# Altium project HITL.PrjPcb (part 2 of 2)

## Sheet HITL (MUX) SH4.SchDoc
size Tabloid; SheetNumber: 4; SheetTotal: 7
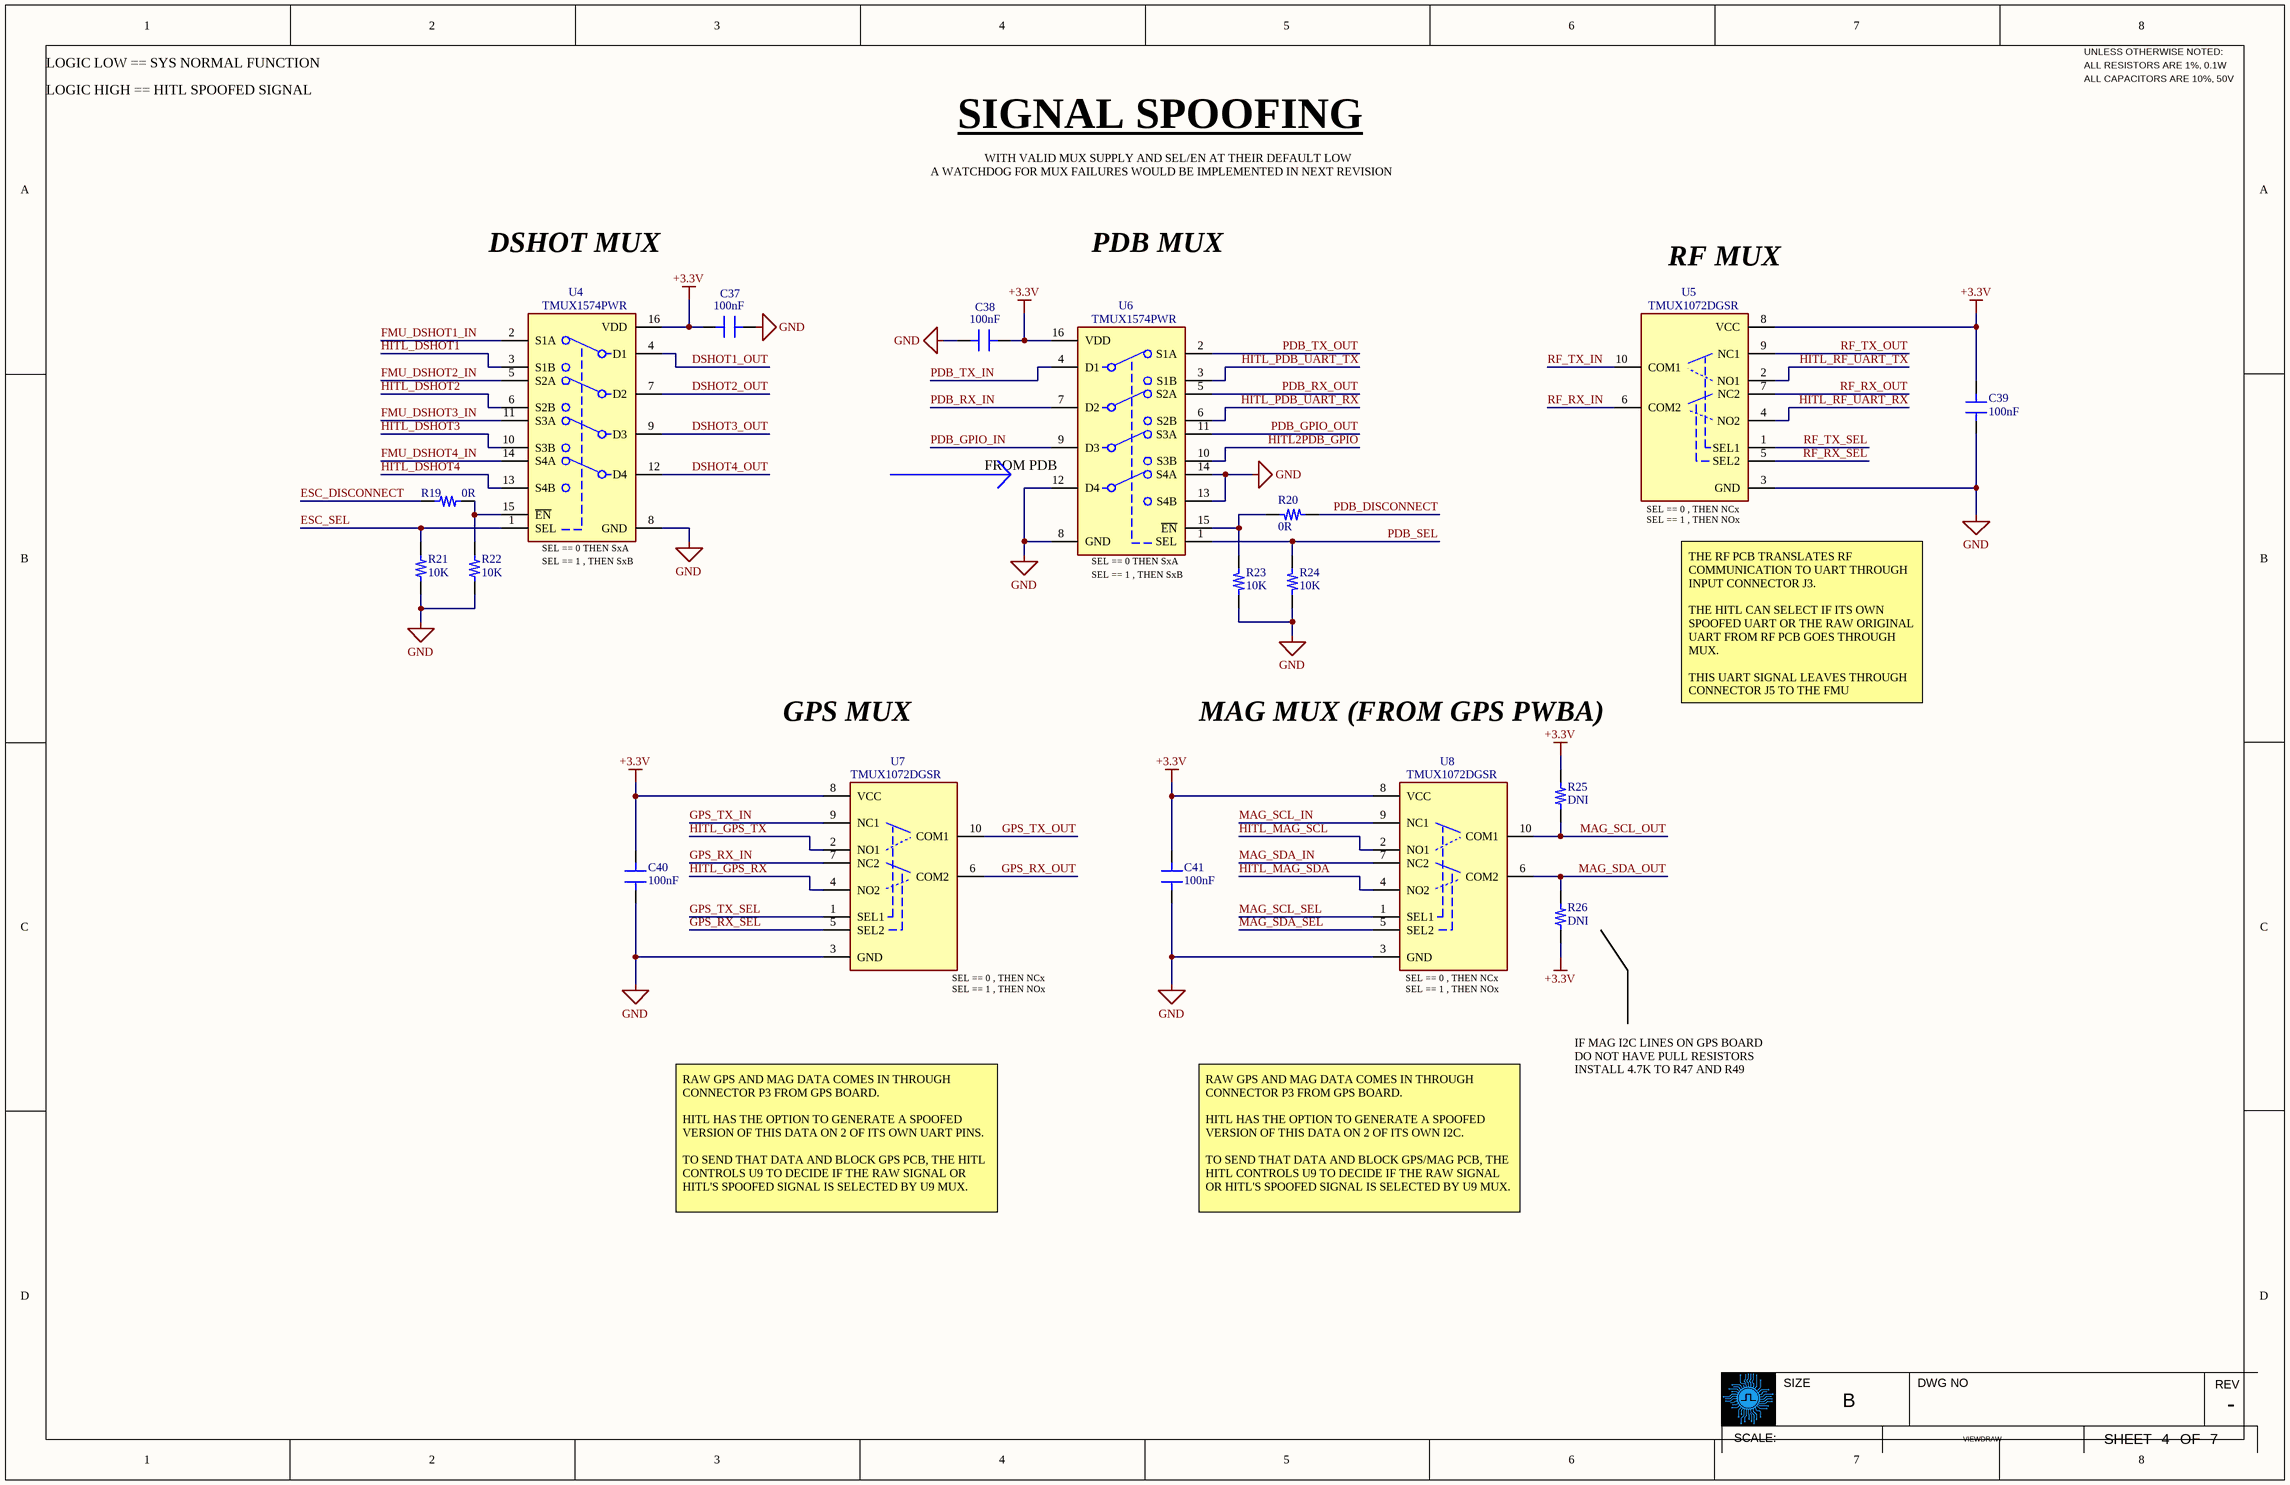
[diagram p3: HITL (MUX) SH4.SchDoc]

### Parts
C37  100nF  [0603]
C38  100nF  [0603]
C39  100nF  [0603]
C40  100nF  [0603]
C41  100nF  [0603]
R19  0R  [0603]
R20  0R  [0603]
R21  10K  [0603]
R22  10K  [0603]
R23  10K  [0603]
R24  10K  [0603]
R25  DNI  [0603]
R26  DNI  [0603]
U4  TMUX1574PWR  [SOP65P640X120-16N]
U5  TMUX1072DGSR  [SOP50P490X110-10N]
U6  TMUX1574PWR  [SOP65P640X120-16N]
U7  TMUX1072DGSR  [SOP50P490X110-10N]
U8  TMUX1072DGSR  [SOP50P490X110-10N]

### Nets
+3.3V: C37.1 C38.1 C39.2 C40.2 C41.2 R25.1 R26.2 U4.16(VDD) U5.8(VCC) U6.16(VDD) U7.8(VCC) U8.8(VCC)
GND: C37.2 C38.2 C39.1 C40.1 C41.1 R21.1 R22.1 R23.1 R24.1 U4.8(GND) U5.3(GND) U6.8(GND) U6.12(D4) U6.13(S4B) U6.14(S4A) U7.3(GND) U8.3(GND)
DSHOT1_OUT: U4.4(D1)
DSHOT2_OUT: U4.7(D2)
DSHOT3_OUT: U4.9(D3)
DSHOT4_OUT: U4.12(D4)
ESC_DISCONNECT: R19.2
ESC_SEL: R21.2 U4.1(SEL)
FMU_DSHOT1_IN: U4.2(S1A)
FMU_DSHOT2_IN: U4.5(S2A)
FMU_DSHOT3_IN: U4.11(S3A)
FMU_DSHOT4_IN: U4.14(S4A)
GPS_RX_IN: U7.7(NC2)
GPS_RX_OUT: U7.6(COM2)
GPS_RX_SEL: U7.5(SEL2)
GPS_TX_IN: U7.9(NC1)
GPS_TX_OUT: U7.10(COM1)
GPS_TX_SEL: U7.1(SEL1)
HITL2PDB_GPIO: U6.10(S3B)
HITL_DSHOT1: U4.3(S1B)
HITL_DSHOT2: U4.6(S2B)
HITL_DSHOT3: U4.10(S3B)
HITL_DSHOT4: U4.13(S4B)
HITL_GPS_RX: U7.4(NO2)
HITL_GPS_TX: U7.2(NO1)
HITL_MAG_SCL: U8.2(NO1)
HITL_MAG_SDA: U8.4(NO2)
HITL_PDB_UART_RX: U6.6(S2B)
HITL_PDB_UART_TX: U6.3(S1B)
HITL_RF_UART_RX: U5.4(NO2)
HITL_RF_UART_TX: U5.2(NO1)
MAG_SCL_IN: U8.9(NC1)
MAG_SCL_OUT: R25.2 U8.10(COM1)
MAG_SCL_SEL: U8.1(SEL1)
MAG_SDA_IN: U8.7(NC2)
MAG_SDA_OUT: R26.1 U8.6(COM2)
MAG_SDA_SEL: U8.5(SEL2)
PDB_DISCONNECT: R20.2
PDB_GPIO_IN: U6.9(D3)
PDB_GPIO_OUT: U6.11(S3A)
PDB_RX_IN: U6.7(D2)
PDB_RX_OUT: U6.5(S2A)
PDB_SEL: R24.2 U6.1(SEL)
PDB_TX_IN: U6.4(D1)
PDB_TX_OUT: U6.2(S1A)
RF_RX_IN: U5.6(COM2)
RF_RX_OUT: U5.7(NC2)
RF_RX_SEL: U5.5(SEL2)
RF_TX_IN: U5.10(COM1)
RF_TX_OUT: U5.9(NC1)
RF_TX_SEL: U5.1(SEL1)
NetR19_1: R19.1 R22.2 U4.15(~{EN})
NetR20_1: R20.1 R23.2 U6.15(~{EN})

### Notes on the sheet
- LOGIC LOW == SYS NORMAL FUNCTION
- LOGIC HIGH == HITL SPOOFED SIGNAL
- SIGNAL SPOOFING
- WITH VALID MUX SUPPLY AND SEL/EN AT THEIR DEFAULT LOW
- A WATCHDOG FOR MUX FAILURES WOULD BE IMPLEMENTED IN NEXT REVISION
- DSHOT MUX
- PDB MUX
- RF MUX
- FROM PDB
- (near U4) SEL == 0 THEN SxA
- (near U4) SEL == 1 , THEN SxB
- (near U6) SEL == 0 THEN SxA
- (near U5) SEL == 0 , THEN NCx
- (near U5) SEL == 1 , THEN NOx
- (near U6) SEL == 1 , THEN SxB
- THE RF PCB TRANSLATES RF COMMUNICATION TO UART THROUGH INPUT CONNECTOR J3.
  THE HITL CAN SELECT IF ITS OWN SPOOFED UART OR THE RAW ORIGINAL UART FROM RF PCB GOES THROUGH MUX.
  THIS UART SIGNAL LEAVES THROUGH CONNECTOR J5 TO THE FMU
- GPS MUX
- MAG MUX (FROM GPS PWBA)
- (near U7) SEL == 0 , THEN NCx
- (near U7) SEL == 1 , THEN NOx
- (near U8) SEL == 0 , THEN NCx
- (near U8) SEL == 1 , THEN NOx
- IF MAG I2C LINES ON GPS BOARD
- DO NOT HAVE PULL RESISTORS
- INSTALL 4.7K TO R47 AND R49
- RAW GPS AND MAG DATA COMES IN THROUGH CONNECTOR P3 FROM GPS BOARD.
  HITL HAS THE OPTION TO GENERATE A SPOOFED VERSION OF THIS DATA ON 2 OF ITS OWN UART PINS.
  TO SEND THAT DATA AND BLOCK GPS PCB, THE HITL CONTROLS U9 TO DECIDE IF THE RAW SIGNAL OR HITL'S SPOOFED SIGNAL IS SELECTED BY U9 MUX.
- RAW GPS AND MAG DATA COMES IN THROUGH CONNECTOR P3 FROM GPS BOARD.
  HITL HAS THE OPTION TO GENERATE A SPOOFED VERSION OF THIS DATA ON 2 OF ITS OWN I2C.
  TO SEND THAT DATA AND BLOCK GPS/MAG PCB, THE HITL CONTROLS U9 TO DECIDE IF THE RAW SIGNAL OR HITL'S SPOOFED SIGNAL IS SELECTED BY U9 MUX.
- -
- 4
- 7

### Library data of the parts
C37-C41 = 0603_C
R19-R26 = 0603_R
U4 U6 = TMUX1574PWR: 5-V, 2:1 (SPDT), 4-channel analog switch with powered-off protection & 1.8-V input logic; MF: Texas Instruments
U5 U7 U8 = TMUX1072DGSR: 5-V, 2:1 (SPDT), 2-channel analog switch with powered-off protection; MF: Texas Instruments

## Sheet HITL (MEMORY) SH5.SchDoc
size Tabloid; SheetNumber: 5; SheetTotal: 7
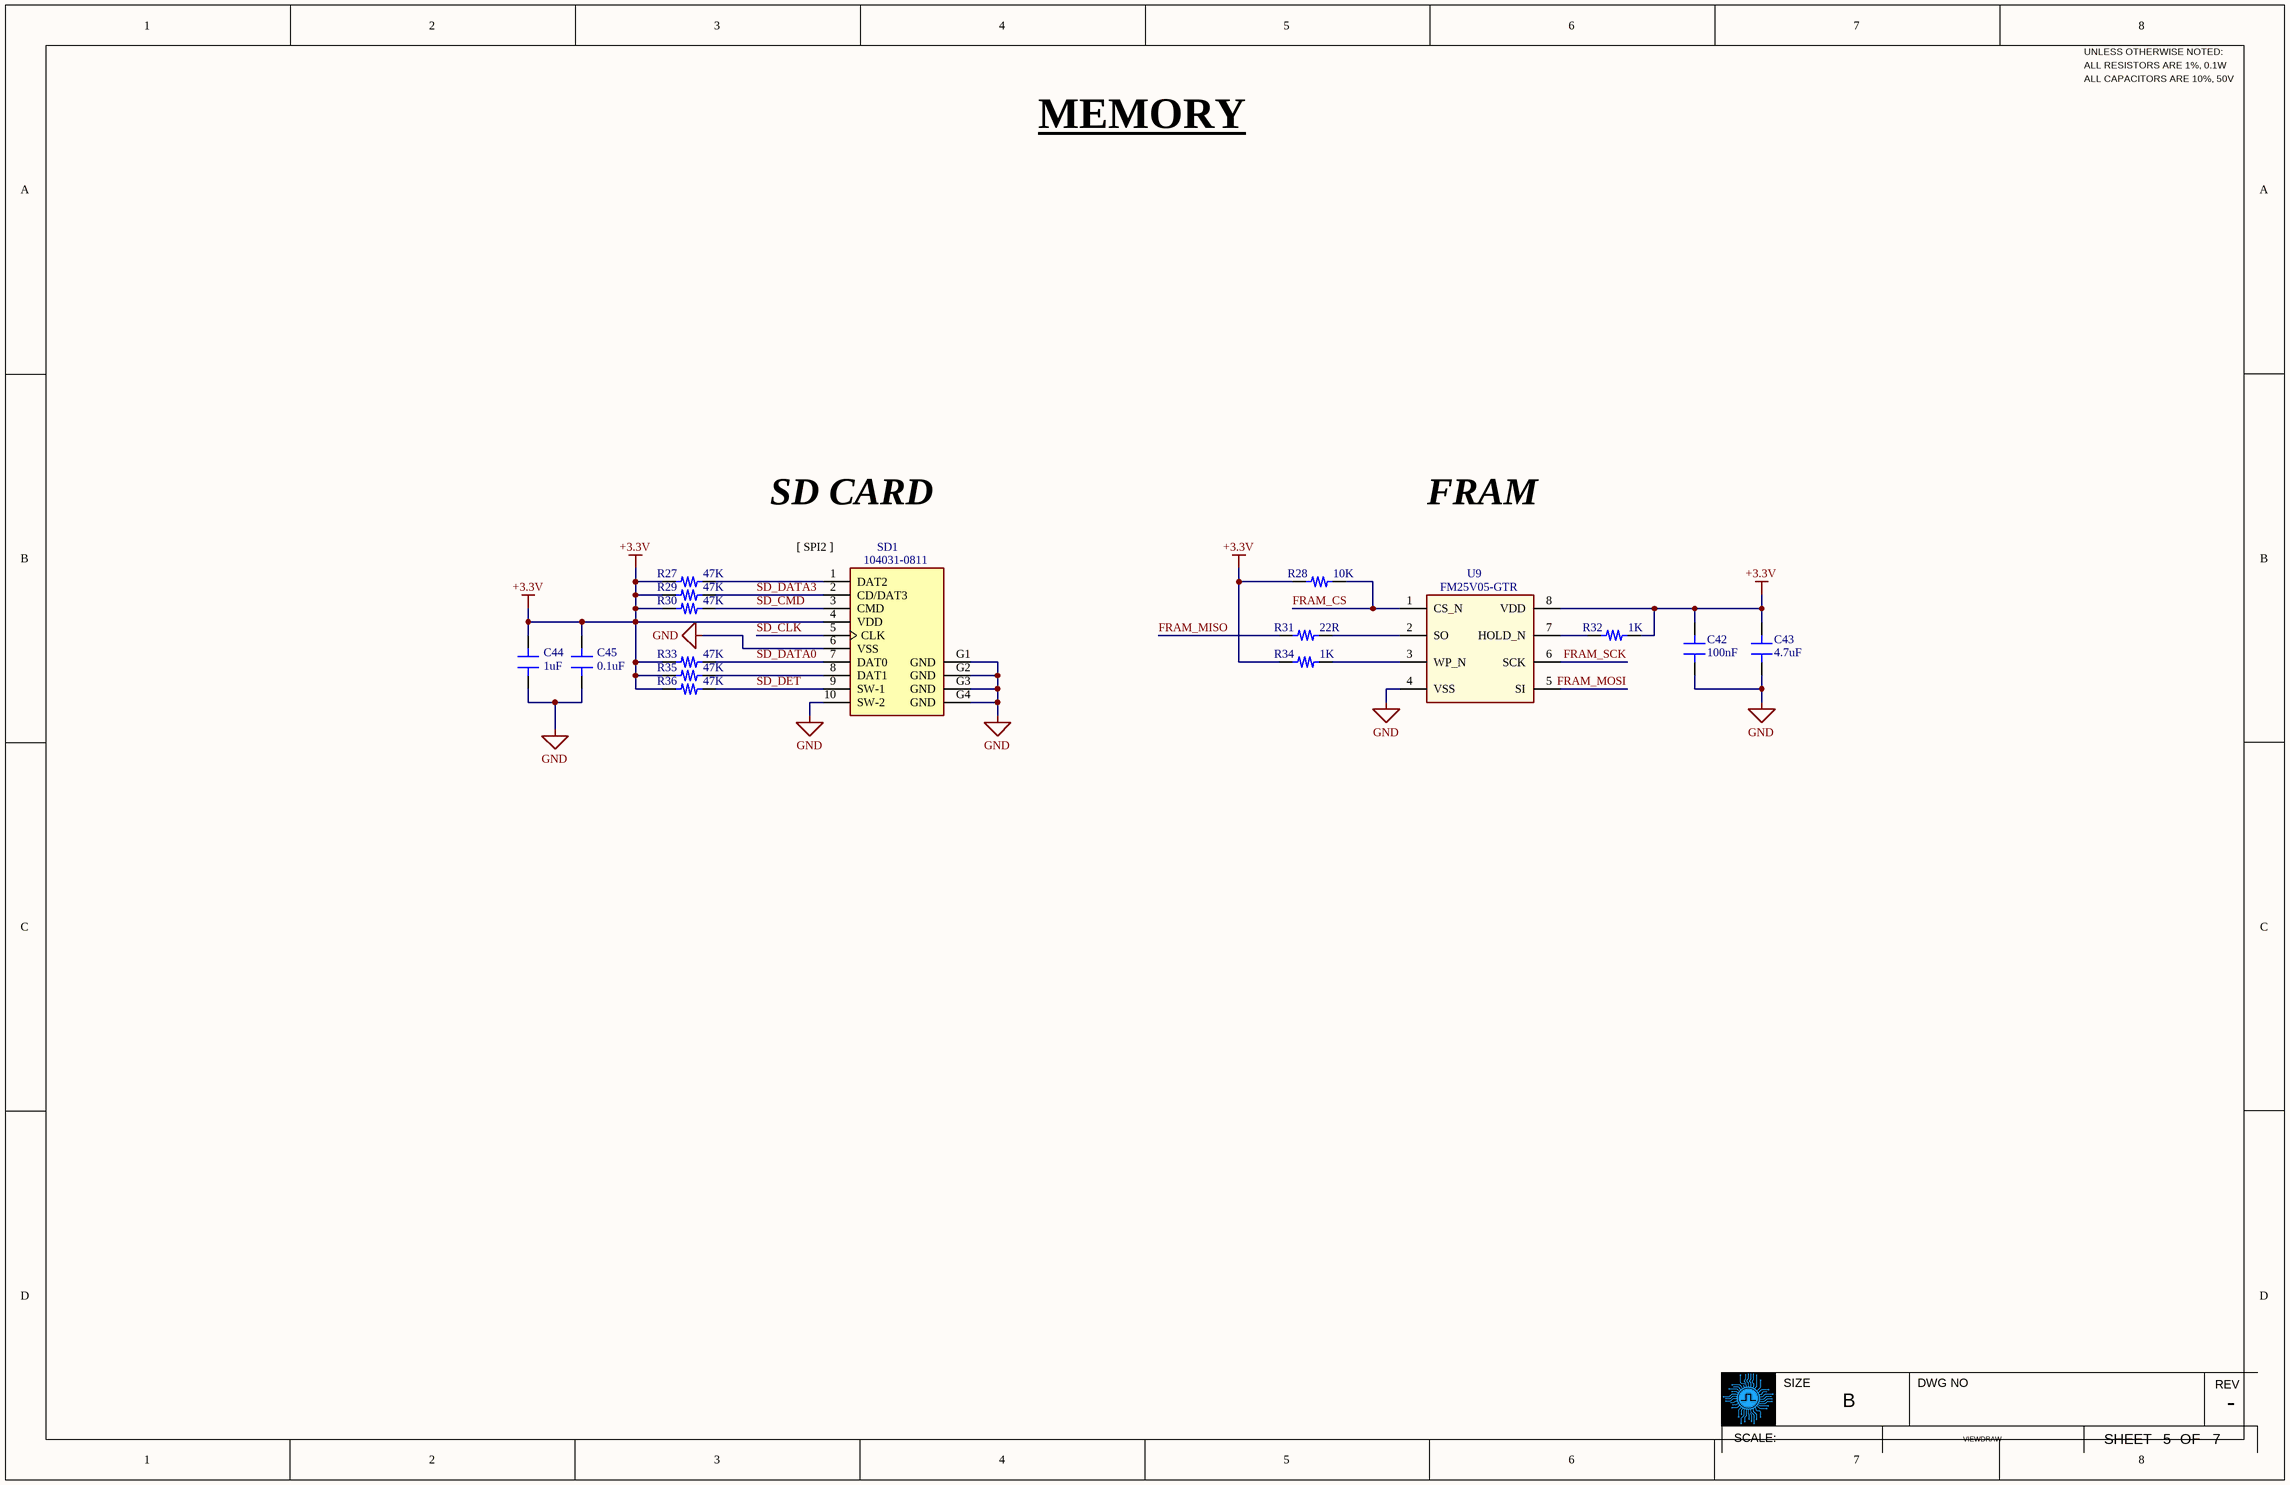
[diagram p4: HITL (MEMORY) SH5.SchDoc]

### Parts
C42  100nF  [0603]
C43  4.7uF  [0603]
C44  1uF  [0603]
C45  0.1uF  [0603]
R27  47K  [0603]
R28  10K  [0603]
R29  47K  [0603]
R30  47K  [0603]
R31  22R  [0603]
R32  1K  [0603]
R33  47K  [0603]
R34  1K  [0603]
R35  47K  [0603]
R36  47K  [0603]
SD1  104031-0811  [MOLEX_104031-0811]
U9  FM25V05-GTR  [SOIC127P602X173-8N-1-V]

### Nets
+3.3V: C42.2 C43.2 C44.2 C45.2 R27.1 R28.1 R29.1 R30.1 R32.2 R33.1 R34.1 R35.1 R36.1 SD1.4(VDD) U9.8(VDD)
GND: C42.1 C43.1 C44.1 C45.1 SD1.6(VSS) SD1.10(SW-2) SD1.G1(GND) SD1.G2(GND) SD1.G3(GND) SD1.G4(GND) U9.4(VSS)
FRAM_CS: R28.2 U9.1(CS_N)
FRAM_MISO: R31.1
FRAM_MOSI: U9.5(SI)
FRAM_SCK: U9.6(SCK)
SD_CLK: SD1.5(CLK)
SD_CMD: R30.2 SD1.3(CMD)
SD_DATA0: R33.2 SD1.7(DAT0)
SD_DATA3: R29.2 SD1.2(CD/DAT3)
SD_DET: R36.2 SD1.9(SW-1)
NetR27_2: R27.2 SD1.1(DAT2)
NetR31_2: R31.2 U9.2(SO)
NetR32_1: R32.1 U9.7(HOLD_N)
NetR34_2: R34.2 U9.3(WP_N)
NetR35_2: R35.2 SD1.8(DAT1)

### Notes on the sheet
- MEMORY
- SD CARD
- (near SD1) [ SPI2 ]
- FRAM
- -
- 5
- 7

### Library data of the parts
C42-C45 = 0603_C
R27-R36 = 0603_R
SD1 = 104031-0811: Surface Mount Micro SD Card Connector, with Push In Termination ¦ Molex Incorporated 104031-0811
U9 = FM25V05-GTR: 4-Kbit (512 × 8) Serial (SPI) F-RAM; Manufacturer: Infineon Technologies

## Sheet HITL (INTRFACE 1) SH6.SchDoc
size Tabloid; SheetNumber: 6; SheetTotal: 7
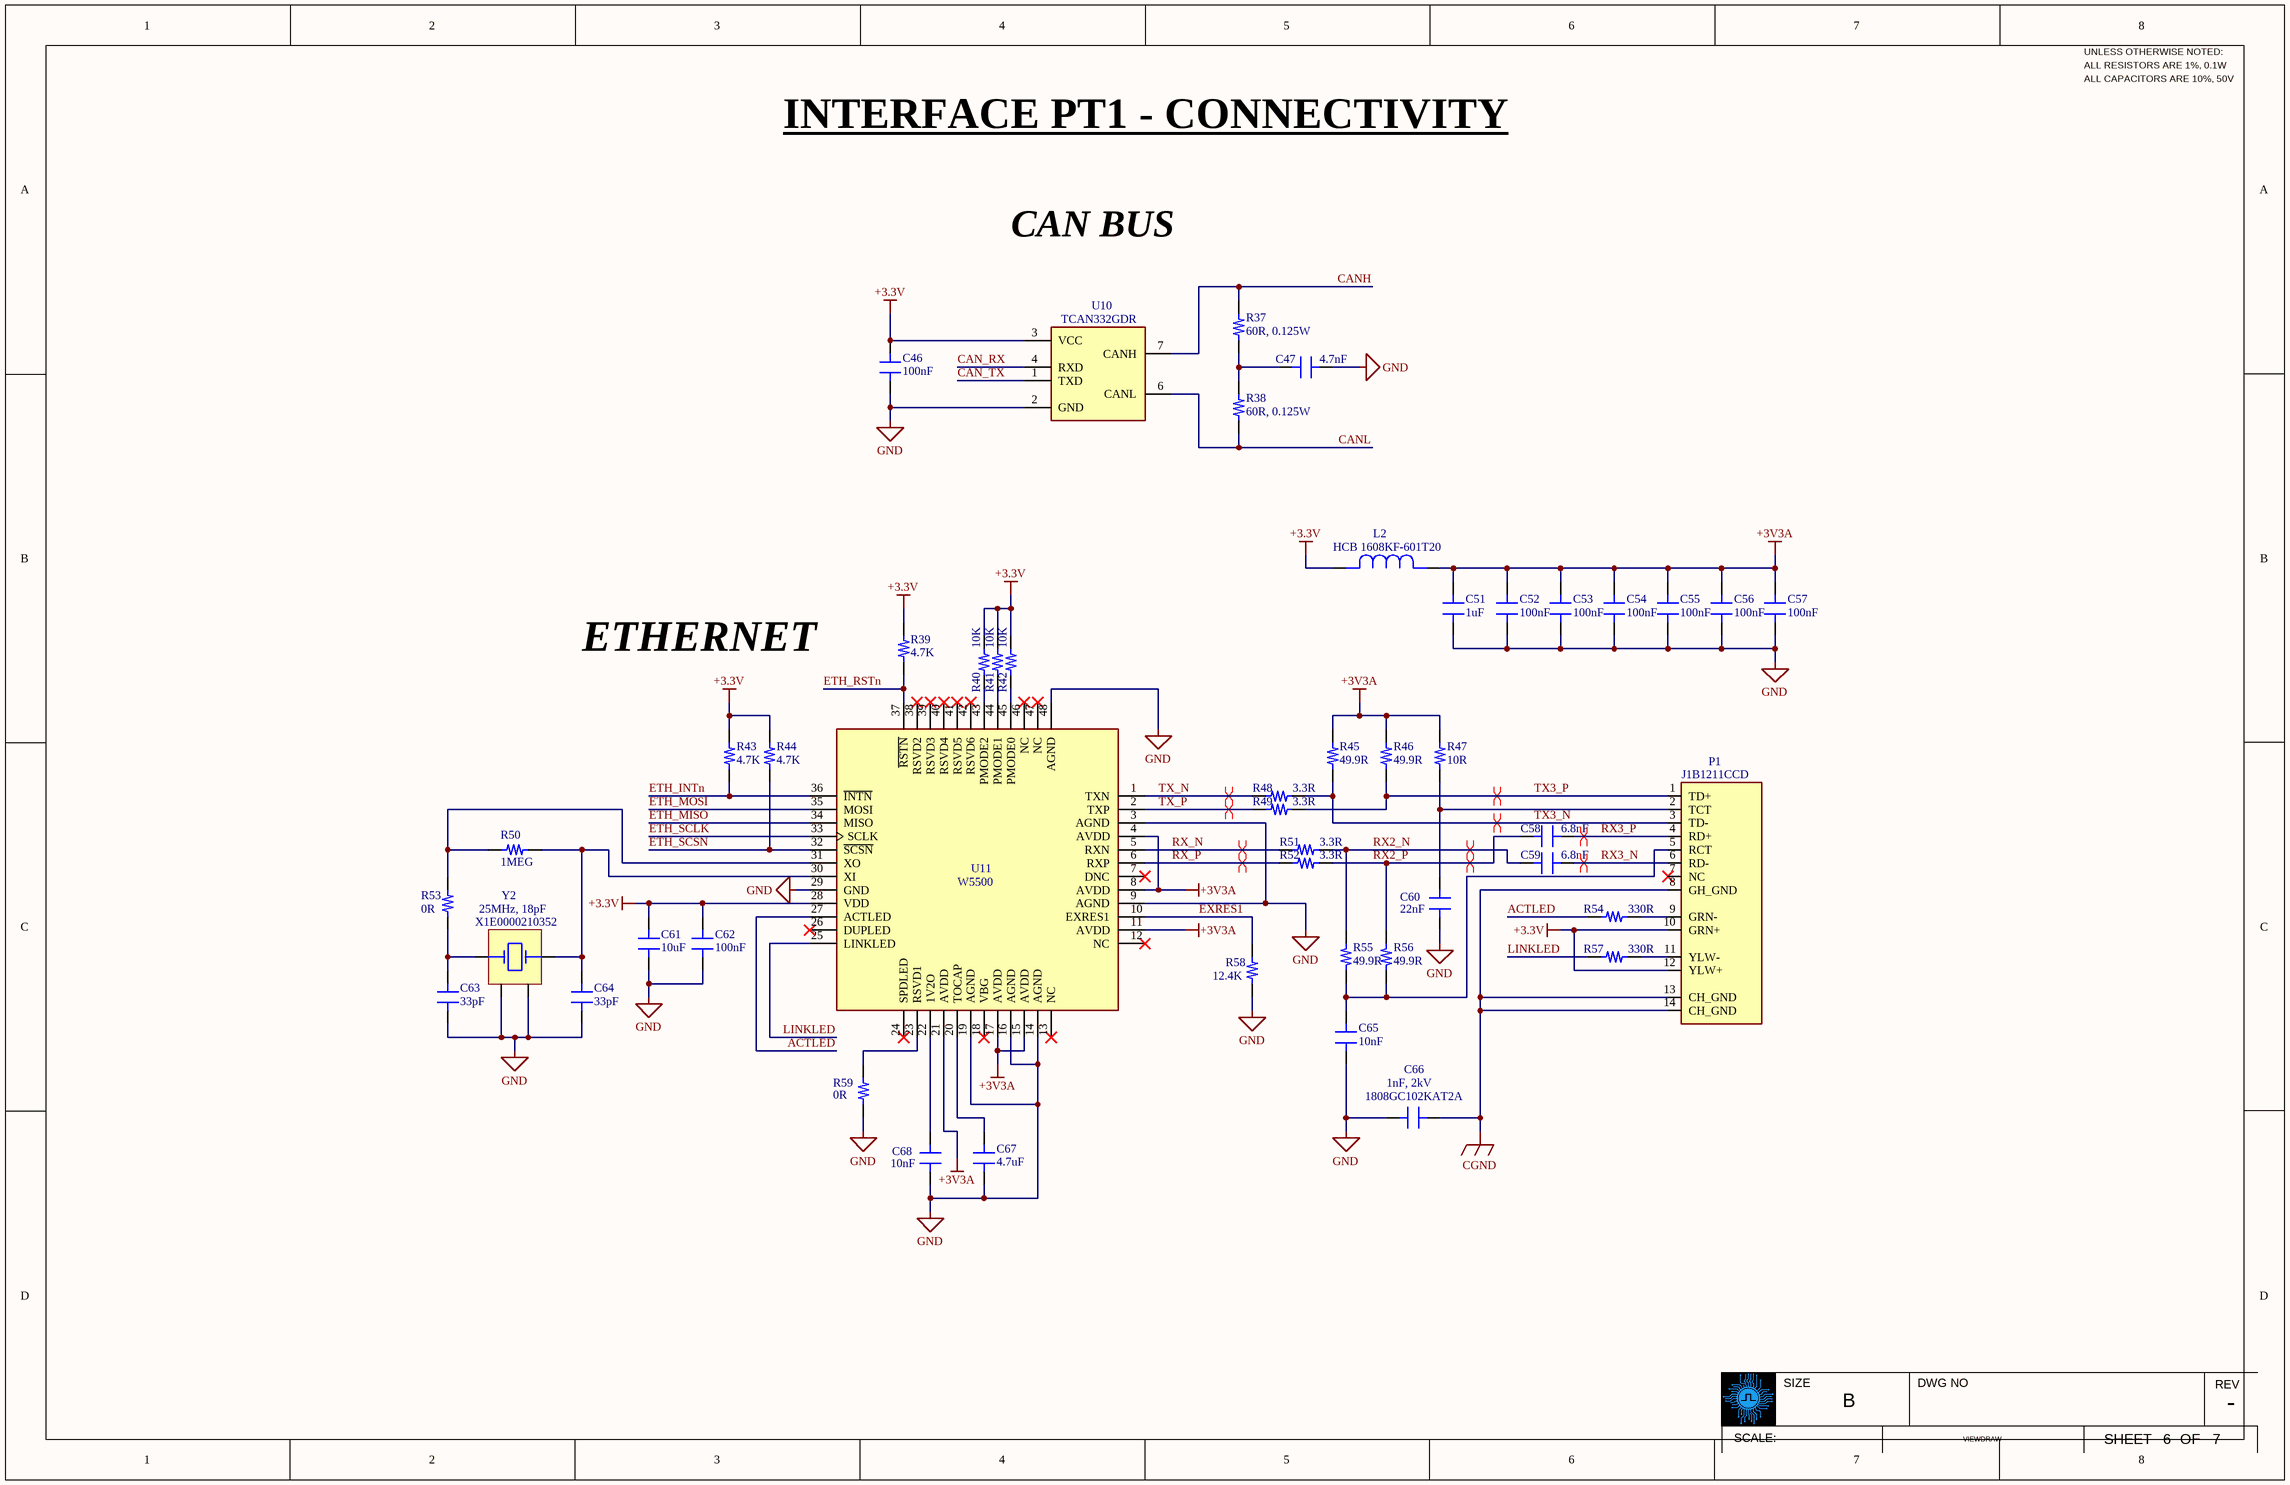
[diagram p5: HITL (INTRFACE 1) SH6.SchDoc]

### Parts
C46  100nF  [0603]
C47  4.7nF  [0603]
C51  1uF  [0603]
C52  100nF  [0603]
C53  100nF  [0603]
C54  100nF  [0603]
C55  100nF  [0603]
C56  100nF  [0603]
C57  100nF  [0603]
C58  6.8nF  [0603]
C59  6.8nF  [0603]
C60  22nF  [0603]
C61  10uF  [0603]
C62  100nF  [0603]
C63  33pF  [0603]
C64  33pF  [0603]
C65  10nF  [0603]
C66  1808GC102KAT2A  [CAP_1808_AVX]
C67  4.7uF  [0603]
C68  10nF  [0603]
L2  HCB 1608KF-601T20  [IND_HCB1608KF_TTA]
P1  J1B1211CCD  [J1B1211CCD]
R37  60R, 0.125W  [0603]
R38  60R, 0.125W  [0603]
R39  4.7K  [0603]
R40  10K  [0603]
R41  10K  [0603]
R42  10K  [0603]
R43  4.7K  [0603]
R44  4.7K  [0603]
R45  49.9R  [0603]
R46  49.9R  [0603]
R47  10R  [0603]
R48  3.3R  [0603]
R49  3.3R  [0603]
R50  1MEG  [0603]
R51  3.3R  [0603]
R52  3.3R  [0603]
R53  0R  [0603]
R54  330R  [0603]
R55  49.9R  [0603]
R56  49.9R  [0603]
R57  330R  [0603]
R58  12.4K  [0603]
R59  0R  [0603]
U10  TCAN332GDR  [SOIC127P599X175-8N]
U11  W5500  [QFP50P900X900X160-48N]
Y2  X1E0000210352  [CRYSTAL4_X1E0000210132 TSX-3225 25 MHZ 9.0PF_EPS]

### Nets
+3.3V: C46.2 C61.2 C62.2 L2.2 P1.10(GRN+) P1.12(YLW+) R39.1 R40.1 R41.1 R42.1 R43.1 R44.1 U10.3(VCC) U11.28(VDD)
+3V3A: C51.2 C52.2 C53.2 C54.2 C55.2 C56.2 C57.2 L2.1 R45.1 R46.1 R47.1 U11.4(AVDD) U11.8(AVDD) U11.11(AVDD) U11.15(AVDD) U11.17(AVDD) U11.21(AVDD)
CGND: C66.2 P1.8(GH_GND) P1.13(CH_GND) P1.14(CH_GND)
GND: C46.1 C47.1 C51.1 C52.1 C53.1 C54.1 C55.1 C56.1 C57.1 C60.1 C61.1 C62.1 C63.1 C64.1 C65.1 C66.1 C67.1 C68.1 R58.1 R59.1 U10.2(GND) U11.3(AGND) U11.9(AGND) U11.14(AGND) U11.16(AGND) U11.19(AGND) U11.29(GND) U11.48(AGND) Y2.2 Y2.4
ACTLED: R54.2 U11.27(ACTLED)
CAN_RX: U10.4(RXD)
CAN_TX: U10.1(TXD)
CANH: R37.1 U10.7(CANH)
CANL: R38.2 U10.6(CANL)
ETH_INTn: R43.2 U11.36(~{INTN})
ETH_MISO: U11.34(MISO)
ETH_MOSI: U11.35(MOSI)
ETH_RSTn: R39.2 U11.37(~{RSTN})
ETH_SCLK: U11.33(SCLK)
ETH_SCSN: R44.2 U11.32(~{SCSN})
EXRES1: R58.2 U11.10(EXRES1)
LINKLED: R57.2 U11.25(LINKLED)
RX2_N: C59.2 R51.1 R55.2
RX2_P: C58.2 R52.1 R56.2
RX3_N: C59.1 P1.6(RD-)
RX3_P: C58.1 P1.4(RD+)
RX_N: R51.2 U11.5(RXN)
RX_P: R52.2 U11.6(RXP)
TX3_N: P1.3(TD-) R45.2 R48.1
TX3_P: P1.1(TD+) R46.2 R49.1
TX_N: R48.2 U11.1(TXN)
TX_P: R49.2 U11.2(TXP)
NetC47_2: C47.2 R37.2 R38.1
NetC60_2: C60.2 P1.2(TCT) R47.2
NetC63_2: C63.2 R53.1 Y2.3
NetC64_2: C64.2 R50.1 U11.30(XI) Y2.1
NetC65_2: C65.2 P1.5(RCT) R55.1 R56.1
NetC67_2: C67.2 U11.20(TOCAP)
NetC68_2: C68.2 U11.22(1V2O)
NetP1_9: P1.9(GRN-) R54.1
NetP1_11: P1.11(YLW-) R57.1
NetR40_2: R40.2 U11.43(PMODE2)
NetR41_2: R41.2 U11.44(PMODE1)
NetR42_2: R42.2 U11.45(PMODE0)
NetR50_2: R50.2 R53.2 U11.31(XO)
NetR59_2: R59.2 U11.23(RSVD1)

Not connected (* = marked no-connect by the designer): P1 7(NC)*; U11 7(DNC)* 12(NC)* 13(NC)* 18(VBG)* 24(SPDLED)* 26(DUPLED)* 38(RSVD2)* 39(RSVD3)* 40(RSVD4)* 41(RSVD5)* 42(RSVD6)* 46(NC)* 47(NC)*

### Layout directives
differential pair: RX2_N, RX2_P, RX3_N, RX3_P, RX_N, RX_P, TX3_N, TX3_P, TX_N, TX_P

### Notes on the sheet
- INTERFACE PT1 - CONNECTIVITY
- CAN BUS
- ETHERNET
- ETHERNET ALLOWS FOR MORE SPEED VS USB. ALSO I WANT TO BE ABLE TO TALK ABOUT ETHERNET IN JOB INTERVIEWS
- 25MHz, 18pF
- (near C66) 1nF, 2kV
- -
- 6
- 7

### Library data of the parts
C46 C47 C51-C65 C67 C68 = 0603_C
C66 = 1808GC102KAT2A: No Description Available; Manufacturer_Name: KYOCERA AVX
L2 = HCB 1608KF-601T20: Description; Manufacturer_Name: Tai Tech
P1 = J1B1211CCD: 1 Port RJ45 Magjack Connector Through Hole 10/100 Base-T, AutoMDIX; MF: WIZnet
R37-R59 = 0603_R
U10 = TCAN332GDR: 3.3-V CAN Transceivers with CAN FD (Flexible Data Rate); MF: Texas Instruments
U11 = W5500: Hardwired TCP/IP embedded Ethernet controller
Y2 = X1E0000210352: Description; Manufacturer_Name: Epson

## Sheet HITL (INTRFACE 2) SH7.SchDoc
size Tabloid; SheetNumber: 7; SheetTotal: 7
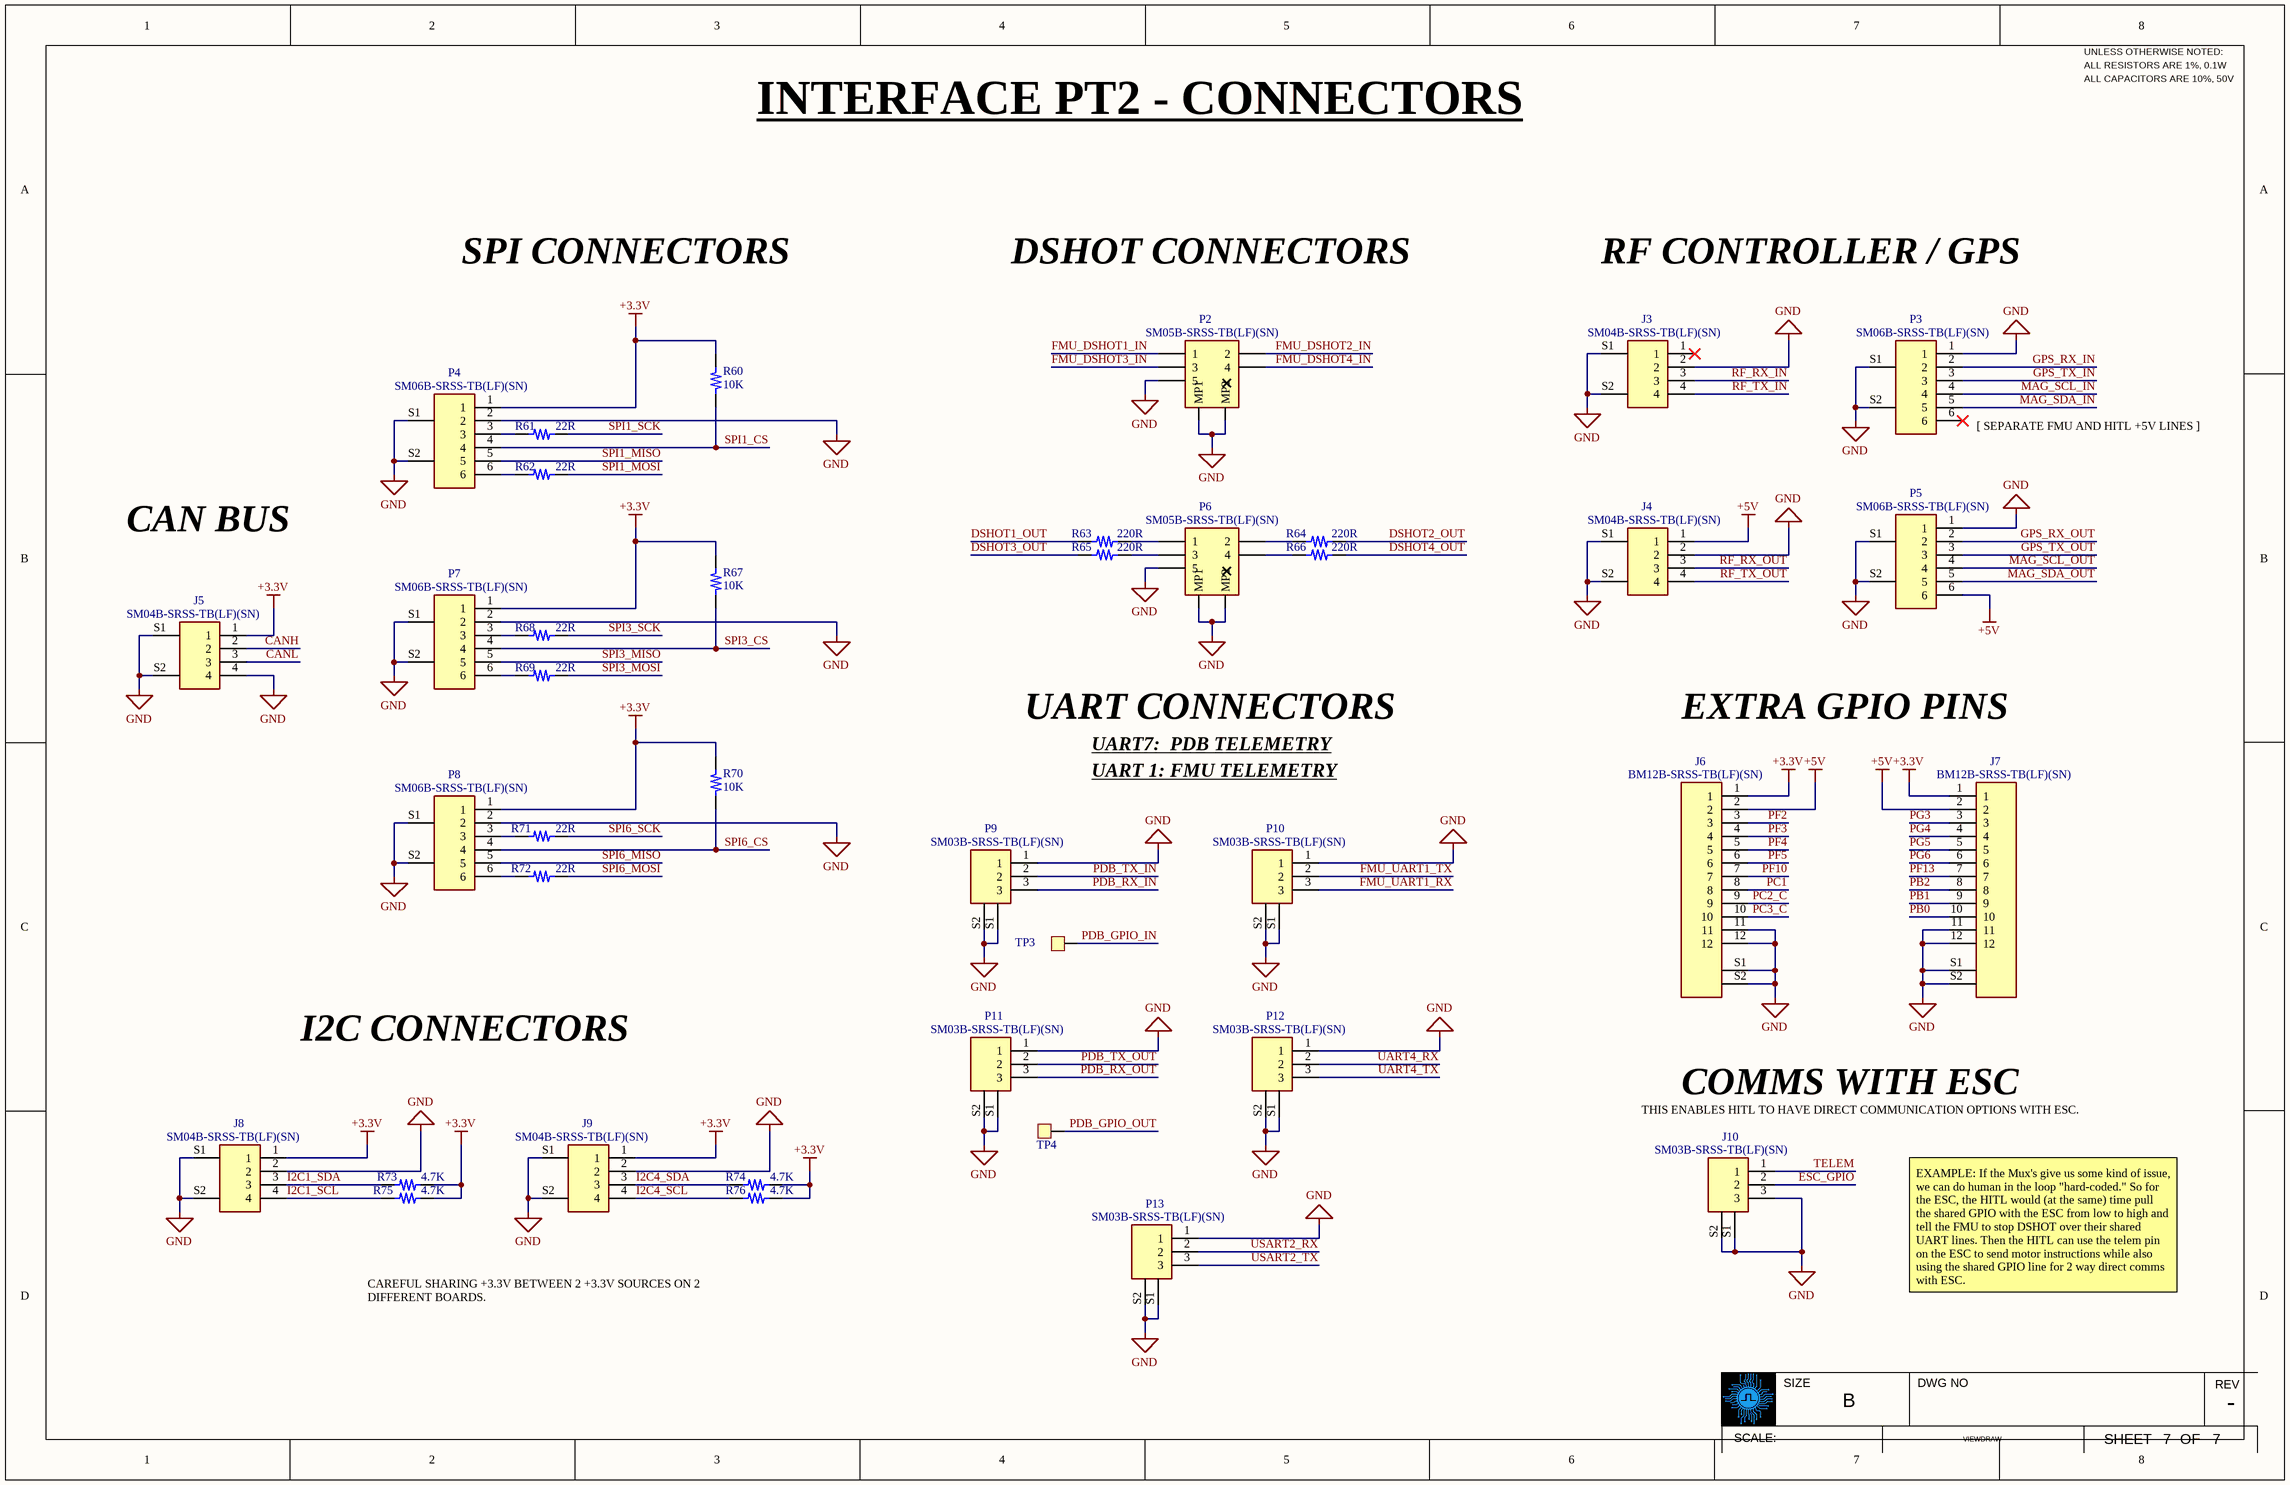
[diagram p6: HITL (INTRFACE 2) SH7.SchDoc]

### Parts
J3  SM04B-SRSS-TB(LF)(SN)  [CONN_SM04B_JST]
J4  SM04B-SRSS-TB(LF)(SN)  [CONN_SM04B_JST]
J5  SM04B-SRSS-TB(LF)(SN)  [CONN_SM04B_JST]
J6  BM12B-SRSS-TB(LF)(SN)  [JST_BM12B-SRSS-TB(LF)(SN)]
J7  BM12B-SRSS-TB(LF)(SN)  [JST_BM12B-SRSS-TB(LF)(SN)]
J8  SM04B-SRSS-TB(LF)(SN)  [CONN_SM04B_JST]
J9  SM04B-SRSS-TB(LF)(SN)  [CONN_SM04B_JST]
J10  SM03B-SRSS-TB(LF)(SN)  [JST_SM03B-SRSS-TB(LF)(SN)]
P2  SM05B-SRSS-TB(LF)(SN)  [CONN5_SM05B-SRSS_JST]
P3  SM06B-SRSS-TB(LF)(SN)  [JST_SM06B-SRSS-TB(LF)(SN)]
P4  SM06B-SRSS-TB(LF)(SN)  [JST_SM06B-SRSS-TB(LF)(SN)]
P5  SM06B-SRSS-TB(LF)(SN)  [JST_SM06B-SRSS-TB(LF)(SN)]
P6  SM05B-SRSS-TB(LF)(SN)  [CONN5_SM05B-SRSS_JST]
P7  SM06B-SRSS-TB(LF)(SN)  [JST_SM06B-SRSS-TB(LF)(SN)]
P8  SM06B-SRSS-TB(LF)(SN)  [JST_SM06B-SRSS-TB(LF)(SN)]
P9  SM03B-SRSS-TB(LF)(SN)  [JST_SM03B-SRSS-TB(LF)(SN)]
P10  SM03B-SRSS-TB(LF)(SN)  [JST_SM03B-SRSS-TB(LF)(SN)]
P11  SM03B-SRSS-TB(LF)(SN)  [JST_SM03B-SRSS-TB(LF)(SN)]
P12  SM03B-SRSS-TB(LF)(SN)  [JST_SM03B-SRSS-TB(LF)(SN)]
P13  SM03B-SRSS-TB(LF)(SN)  [JST_SM03B-SRSS-TB(LF)(SN)]
R60  10K  [0603]
R61  22R  [0603]
R62  22R  [0603]
R63  220R  [0603]
R64  220R  [0603]
R65  220R  [0603]
R66  220R  [0603]
R67  10K  [0603]
R68  22R  [0603]
R69  22R  [0603]
R70  10K  [0603]
R71  22R  [0603]
R72  22R  [0603]
R73  4.7K  [0603]
R74  4.7K  [0603]
R75  4.7K  [0603]
R76  4.7K  [0603]
TP3  FMU_PAD  [FMU_PAD]  (value not drawn)
TP4  FMU_PAD  [FMU_PAD]  (value not drawn)

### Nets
+3.3V: J5.1 J6.1 J7.1 J8.1 J9.1 P4.1 P7.1 P8.1 R60.2 R67.2 R70.2 R73.2 R74.2 R75.2 R76.2
+5V: J4.1 J6.2 J7.2 P5.6
GND: J3.2 J3.S1(SHIELD) J3.S2(SHIELD) J4.2 J4.S1(SHIELD) J4.S2(SHIELD) J5.4 J5.S1(SHIELD) J5.S2(SHIELD) J6.11 J6.12 J6.S1(SHIELD) J6.S2(SHIELD) J7.11 J7.12 J7.S1(SHIELD) J7.S2(SHIELD) J8.2 J8.S1(SHIELD) J8.S2(SHIELD) J9.2 J9.S1(SHIELD) J9.S2(SHIELD) J10.3 J10.S1(SHIELD) J10.S2(SHIELD) P2.5 P2.6(MP1) P2.7(MP2) P3.1 P3.S1(SHIELD) P3.S2(SHIELD) P4.2 P4.S1(SHIELD) P4.S2(SHIELD) P5.1 P5.S1(SHIELD) P5.S2(SHIELD) P6.5 P6.6(MP1) P6.7(MP2) P7.2 P7.S1(SHIELD) P7.S2(SHIELD) P8.2 P8.S1(SHIELD) P8.S2(SHIELD) P9.1 P9.S1(SHIELD) P9.S2(SHIELD) P10.1 P10.S1(SHIELD) P10.S2(SHIELD) P11.1 P11.S1(SHIELD) P11.S2(SHIELD) P12.1 P12.S1(SHIELD) P12.S2(SHIELD) P13.1 P13.S1(SHIELD) P13.S2(SHIELD)
CANH: J5.2
CANL: J5.3
DSHOT1_OUT: R63.1
DSHOT2_OUT: R64.2
DSHOT3_OUT: R65.1
DSHOT4_OUT: R66.2
ESC_GPIO: J10.2
FMU_DSHOT1_IN: P2.1
FMU_DSHOT2_IN: P2.2
FMU_DSHOT3_IN: P2.3
FMU_DSHOT4_IN: P2.4
FMU_UART1_RX: P10.3
FMU_UART1_TX: P10.2
GPS_RX_IN: P3.2
GPS_RX_OUT: P5.2
GPS_TX_IN: P3.3
GPS_TX_OUT: P5.3
I2C1_SCL: J8.4 R75.1
I2C1_SDA: J8.3 R73.1
I2C4_SCL: J9.4 R76.1
I2C4_SDA: J9.3 R74.1
MAG_SCL_IN: P3.4
MAG_SCL_OUT: P5.4
MAG_SDA_IN: P3.5
MAG_SDA_OUT: P5.5
PB0: J7.10
PB1: J7.9
PB2: J7.8
PC1: J6.8
PC2_C: J6.9
PC3_C: J6.10
PDB_GPIO_IN: TP3.1
PDB_GPIO_OUT: TP4.1
PDB_RX_IN: P9.3
PDB_RX_OUT: P11.3
PDB_TX_IN: P9.2
PDB_TX_OUT: P11.2
PF2: J6.3
PF3: J6.4
PF4: J6.5
PF5: J6.6
PF10: J6.7
PF13: J7.7
PG3: J7.3
PG4: J7.4
PG5: J7.5
PG6: J7.6
RF_RX_IN: J3.3
RF_RX_OUT: J4.3
RF_TX_IN: J3.4
RF_TX_OUT: J4.4
SPI1_CS: P4.4 R60.1
SPI1_MISO: P4.5
SPI1_MOSI: R62.2
SPI1_SCK: R61.2
SPI3_CS: P7.4 R67.1
SPI3_MISO: P7.5
SPI3_MOSI: R69.2
SPI3_SCK: R68.2
SPI6_CS: P8.4 R70.1
SPI6_MISO: P8.5
SPI6_MOSI: R72.2
SPI6_SCK: R71.2
TELEM: J10.1
UART4_RX: P12.2
UART4_TX: P12.3
USART2_RX: P13.2
USART2_TX: P13.3
NetP4_3: P4.3 R61.1
NetP4_6: P4.6 R62.1
NetP6_1: P6.1 R63.2
NetP6_2: P6.2 R64.1
NetP6_3: P6.3 R65.2
NetP6_4: P6.4 R66.1
NetP7_3: P7.3 R68.1
NetP7_6: P7.6 R69.1
NetP8_3: P8.3 R71.1
NetP8_6: P8.6 R72.1

Not connected (* = marked no-connect by the designer): J3 1*; P3 6*

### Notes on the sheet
- INTERFACE PT2 - CONNECTORS
- SPI CONNECTORS
- DSHOT CONNECTORS
- RF CONTROLLER / GPS
- (near P3) [ SEPARATE FMU AND HITL +5V LINES ]
- CAN BUS
- UART CONNECTORS
- UART7:  PDB TELEMETRY
- EXTRA GPIO PINS
- UART 1: FMU TELEMETRY
- I2C CONNECTORS
- COMMS WITH ESC
- THIS ENABLES HITL TO HAVE DIRECT COMMUNICATION OPTIONS WITH ESC.
- CAREFUL SHARING +3.3V BETWEEN 2 +3.3V SOURCES ON 2
- DIFFERENT BOARDS.
- EXAMPLE: If the Mux's give us some kind of issue, we can do human in the loop "hard-coded." So for the ESC, the HITL would (at the same) time pull the shared GPIO with the ESC from low to high and tell the FMU to stop DSHOT over their shared UART lines. Then the HITL can use the telem pin on the ESC to send motor instructions while also using the shared GPIO line for 2 way direct comms with ESC.
- -
- 7

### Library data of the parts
J3-J5 J8 J9 = SM04B-SRSS-TBLFSN: Description; Manufacturer_Name: JST
J10 P9-P13 = SM03B-SRSS-TB(LF)(SN): Connector Header Surface Mount, Right Angle 3 position 0.039 (1.00mm); MF: JST Sales
P2 P6 = SM05B-SRSS-TBLFSN: Description; Manufacturer_Name: JST
P3-P5 P7 P8 = SM06B-SRSS-TB(LF)(SN): Connector Header Surface Mount, Right Angle 6 position 0.039 (1.00mm); MF: JST Sales
R60-R76 = 0603_R
TP3 TP4 = FMU_PAD: 1.5mm X 1.5mm PAD FOR COMM PROTOCOLS, GPIOS, ADC, TIMERS, ETC

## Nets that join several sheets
+3.3V: HITL (PWR) SH2 (9 pins), HITL (MCU) SH3 (37 pins), HITL (MUX) SH4 (12 pins), HITL (MEMORY) SH5 (15 pins), HITL (INTRFACE 1) SH6 (14 pins), HITL (INTRFACE 2) SH7 (15 pins)
+5V: HITL (PWR) SH2 (17 pins), HITL (INTRFACE 2) SH7 (J4.1 J6.2 J7.2 P5.6)
GND: HITL (PWR) SH2 (36 pins), HITL (MCU) SH3 (46 pins), HITL (MUX) SH4 (17 pins), HITL (MEMORY) SH5 (11 pins), HITL (INTRFACE 1) SH6 (30 pins), HITL (INTRFACE 2) SH7 (62 pins)
CAN_RX: HITL (MCU) SH3 (U3.114), HITL (INTRFACE 1) SH6 (U10.4)
CAN_TX: HITL (MCU) SH3 (U3.115), HITL (INTRFACE 1) SH6 (U10.1)
CANH: HITL (INTRFACE 1) SH6 (R37.1 U10.7), HITL (INTRFACE 2) SH7 (J5.2)
CANL: HITL (INTRFACE 1) SH6 (R38.2 U10.6), HITL (INTRFACE 2) SH7 (J5.3)
DOUT_N: HITL (PWR) SH2 (U1.6), HITL (MCU) SH3 (U3.103)
DOUT_P: HITL (PWR) SH2 (U1.4), HITL (MCU) SH3 (U3.104)
DSHOT1_OUT: HITL (MUX) SH4 (U4.4), HITL (INTRFACE 2) SH7 (R63.1)
DSHOT2_OUT: HITL (MUX) SH4 (U4.7), HITL (INTRFACE 2) SH7 (R64.2)
DSHOT3_OUT: HITL (MUX) SH4 (U4.9), HITL (INTRFACE 2) SH7 (R65.1)
DSHOT4_OUT: HITL (MUX) SH4 (U4.12), HITL (INTRFACE 2) SH7 (R66.2)
ESC_DISCONNECT: HITL (MCU) SH3 (U3.69), HITL (MUX) SH4 (R19.2)
ESC_GPIO: HITL (MCU) SH3 (R12.1 U3.78), HITL (INTRFACE 2) SH7 (J10.2)
ESC_SEL: HITL (MCU) SH3 (U3.70), HITL (MUX) SH4 (R21.2 U4.1)
ETH_INTn: HITL (MCU) SH3 (U3.56), HITL (INTRFACE 1) SH6 (R43.2 U11.36)
ETH_MISO: HITL (MCU) SH3 (U3.20), HITL (INTRFACE 1) SH6 (U11.34)
ETH_MOSI: HITL (MCU) SH3 (U3.21), HITL (INTRFACE 1) SH6 (U11.35)
ETH_RSTn: HITL (MCU) SH3 (U3.57), HITL (INTRFACE 1) SH6 (R39.2 U11.37)
ETH_SCLK: HITL (MCU) SH3 (U3.19), HITL (INTRFACE 1) SH6 (U11.33)
ETH_SCSN: HITL (MCU) SH3 (U3.18), HITL (INTRFACE 1) SH6 (R44.2 U11.32)
FMU_DSHOT1_IN: HITL (MUX) SH4 (U4.2), HITL (INTRFACE 2) SH7 (P2.1)
FMU_DSHOT2_IN: HITL (MUX) SH4 (U4.5), HITL (INTRFACE 2) SH7 (P2.2)
FMU_DSHOT3_IN: HITL (MUX) SH4 (U4.11), HITL (INTRFACE 2) SH7 (P2.3)
FMU_DSHOT4_IN: HITL (MUX) SH4 (U4.14), HITL (INTRFACE 2) SH7 (P2.4)
FMU_UART1_RX: HITL (MCU) SH3 (U3.137), HITL (INTRFACE 2) SH7 (P10.3)
FMU_UART1_TX: HITL (MCU) SH3 (U3.136), HITL (INTRFACE 2) SH7 (P10.2)
FRAM_CS: HITL (MCU) SH3 (U3.3), HITL (MEMORY) SH5 (R28.2 U9.1)
FRAM_MISO: HITL (MCU) SH3 (U3.4), HITL (MEMORY) SH5 (R31.1)
FRAM_MOSI: HITL (MCU) SH3 (R11.1), HITL (MEMORY) SH5 (U9.5)
FRAM_SCK: HITL (MCU) SH3 (R10.1), HITL (MEMORY) SH5 (U9.6)
GPS_RX_IN: HITL (MUX) SH4 (U7.7), HITL (INTRFACE 2) SH7 (P3.2)
GPS_RX_OUT: HITL (MUX) SH4 (U7.6), HITL (INTRFACE 2) SH7 (P5.2)
GPS_RX_SEL: HITL (MCU) SH3 (U3.54), HITL (MUX) SH4 (U7.5)
GPS_TX_IN: HITL (MUX) SH4 (U7.9), HITL (INTRFACE 2) SH7 (P3.3)
GPS_TX_OUT: HITL (MUX) SH4 (U7.10), HITL (INTRFACE 2) SH7 (P5.3)
GPS_TX_SEL: HITL (MCU) SH3 (U3.55), HITL (MUX) SH4 (U7.1)
HITL2PDB_GPIO: HITL (MCU) SH3 (U3.63), HITL (MUX) SH4 (U6.10)
HITL_DSHOT1: HITL (MCU) SH3 (U3.60), HITL (MUX) SH4 (U4.3)
HITL_DSHOT2: HITL (MCU) SH3 (U3.64), HITL (MUX) SH4 (U4.6)
HITL_DSHOT3: HITL (MCU) SH3 (U3.66), HITL (MUX) SH4 (U4.10)
HITL_DSHOT4: HITL (MCU) SH3 (U3.67), HITL (MUX) SH4 (U4.13)
HITL_GPS_RX: HITL (MCU) SH3 (U3.97), HITL (MUX) SH4 (U7.4)
HITL_GPS_TX: HITL (MCU) SH3 (U3.96), HITL (MUX) SH4 (U7.2)
HITL_MAG_SCL: HITL (MCU) SH3 (U3.100), HITL (MUX) SH4 (U8.2)
HITL_MAG_SDA: HITL (MCU) SH3 (U3.99), HITL (MUX) SH4 (U8.4)
HITL_PDB_UART_RX: HITL (MCU) SH3 (U3.58), HITL (MUX) SH4 (U6.6)
HITL_PDB_UART_TX: HITL (MCU) SH3 (U3.59), HITL (MUX) SH4 (U6.3)
HITL_RF_UART_RX: HITL (MCU) SH3 (U3.141), HITL (MUX) SH4 (U5.4)
HITL_RF_UART_TX: HITL (MCU) SH3 (U3.142), HITL (MUX) SH4 (U5.2)
I2C1_SCL: HITL (MCU) SH3 (U3.139), HITL (INTRFACE 2) SH7 (J8.4 R75.1)
I2C1_SDA: HITL (MCU) SH3 (U3.140), HITL (INTRFACE 2) SH7 (J8.3 R73.1)
I2C4_SCL: HITL (MCU) SH3 (U3.81), HITL (INTRFACE 2) SH7 (J9.4 R76.1)
I2C4_SDA: HITL (MCU) SH3 (U3.82), HITL (INTRFACE 2) SH7 (J9.3 R74.1)
MAG_SCL_IN: HITL (MUX) SH4 (U8.9), HITL (INTRFACE 2) SH7 (P3.4)
MAG_SCL_OUT: HITL (MUX) SH4 (R25.2 U8.10), HITL (INTRFACE 2) SH7 (P5.4)
MAG_SCL_SEL: HITL (MCU) SH3 (U3.49), HITL (MUX) SH4 (U8.1)
MAG_SDA_IN: HITL (MUX) SH4 (U8.7), HITL (INTRFACE 2) SH7 (P3.5)
MAG_SDA_OUT: HITL (MUX) SH4 (R26.1 U8.6), HITL (INTRFACE 2) SH7 (P5.5)
MAG_SDA_SEL: HITL (MCU) SH3 (U3.50), HITL (MUX) SH4 (U8.5)
PB0: HITL (MCU) SH3 (U3.46), HITL (INTRFACE 2) SH7 (J7.10)
PB1: HITL (MCU) SH3 (U3.47), HITL (INTRFACE 2) SH7 (J7.9)
PB2: HITL (MCU) SH3 (U3.48), HITL (INTRFACE 2) SH7 (J7.8)
PC1: HITL (MCU) SH3 (U3.27), HITL (INTRFACE 2) SH7 (J6.8)
PC2_C: HITL (MCU) SH3 (U3.28), HITL (INTRFACE 2) SH7 (J6.9)
PC3_C: HITL (MCU) SH3 (U3.29), HITL (INTRFACE 2) SH7 (J6.10)
PDB_DISCONNECT: HITL (MCU) SH3 (U3.65), HITL (MUX) SH4 (R20.2)
PDB_GPIO_IN: HITL (MUX) SH4 (U6.9), HITL (INTRFACE 2) SH7 (TP3.1)
PDB_GPIO_OUT: HITL (MUX) SH4 (U6.11), HITL (INTRFACE 2) SH7 (TP4.1)
PDB_RX_IN: HITL (MUX) SH4 (U6.7), HITL (INTRFACE 2) SH7 (P9.3)
PDB_RX_OUT: HITL (MUX) SH4 (U6.5), HITL (INTRFACE 2) SH7 (P11.3)
PDB_SEL: HITL (MCU) SH3 (U3.68), HITL (MUX) SH4 (R24.2 U6.1)
PDB_TX_IN: HITL (MUX) SH4 (U6.4), HITL (INTRFACE 2) SH7 (P9.2)
PDB_TX_OUT: HITL (MUX) SH4 (U6.2), HITL (INTRFACE 2) SH7 (P11.2)
PF2: HITL (MCU) SH3 (U3.12), HITL (INTRFACE 2) SH7 (J6.3)
PF3: HITL (MCU) SH3 (U3.13), HITL (INTRFACE 2) SH7 (J6.4)
PF4: HITL (MCU) SH3 (U3.14), HITL (INTRFACE 2) SH7 (J6.5)
PF5: HITL (MCU) SH3 (U3.15), HITL (INTRFACE 2) SH7 (J6.6)
PF10: HITL (MCU) SH3 (U3.22), HITL (INTRFACE 2) SH7 (J6.7)
PF13: HITL (MCU) SH3 (U3.53), HITL (INTRFACE 2) SH7 (J7.7)
PG3: HITL (MCU) SH3 (U3.88), HITL (INTRFACE 2) SH7 (J7.3)
PG4: HITL (MCU) SH3 (U3.89), HITL (INTRFACE 2) SH7 (J7.4)
PG5: HITL (MCU) SH3 (U3.90), HITL (INTRFACE 2) SH7 (J7.5)
PG6: HITL (MCU) SH3 (U3.91), HITL (INTRFACE 2) SH7 (J7.6)
RF_RX_IN: HITL (MUX) SH4 (U5.6), HITL (INTRFACE 2) SH7 (J3.3)
RF_RX_OUT: HITL (MUX) SH4 (U5.7), HITL (INTRFACE 2) SH7 (J4.3)
RF_RX_SEL: HITL (MCU) SH3 (U3.44), HITL (MUX) SH4 (U5.5)
RF_TX_IN: HITL (MUX) SH4 (U5.10), HITL (INTRFACE 2) SH7 (J3.4)
RF_TX_OUT: HITL (MUX) SH4 (U5.9), HITL (INTRFACE 2) SH7 (J4.4)
RF_TX_SEL: HITL (MCU) SH3 (U3.45), HITL (MUX) SH4 (U5.1)
SD_CLK: HITL (MCU) SH3 (U3.74), HITL (MEMORY) SH5 (SD1.5)
SD_CMD: HITL (MCU) SH3 (U3.76), HITL (MEMORY) SH5 (R30.2 SD1.3)
SD_DATA0: HITL (MCU) SH3 (U3.75), HITL (MEMORY) SH5 (R33.2 SD1.7)
SD_DATA3: HITL (MCU) SH3 (U3.73), HITL (MEMORY) SH5 (R29.2 SD1.2)
SD_DET: HITL (MCU) SH3 (U3.92), HITL (MEMORY) SH5 (R36.2 SD1.9)
SPI1_CS: HITL (MCU) SH3 (U3.40), HITL (INTRFACE 2) SH7 (P4.4 R60.1)
SPI1_MISO: HITL (MCU) SH3 (R15.1), HITL (INTRFACE 2) SH7 (P4.5)
SPI1_MOSI: HITL (MCU) SH3 (U3.43), HITL (INTRFACE 2) SH7 (R62.2)
SPI1_SCK: HITL (MCU) SH3 (U3.41), HITL (INTRFACE 2) SH7 (R61.2)
SPI3_CS: HITL (MCU) SH3 (U3.110), HITL (INTRFACE 2) SH7 (P7.4 R67.1)
SPI3_MISO: HITL (MCU) SH3 (U3.112), HITL (INTRFACE 2) SH7 (P7.5)
SPI3_MOSI: HITL (MCU) SH3 (U3.113), HITL (INTRFACE 2) SH7 (R69.2)
SPI3_SCK: HITL (MCU) SH3 (U3.111), HITL (INTRFACE 2) SH7 (R68.2)
SPI6_CS: HITL (MCU) SH3 (U3.126), HITL (INTRFACE 2) SH7 (P8.4 R70.1)
SPI6_MISO: HITL (MCU) SH3 (U3.127), HITL (INTRFACE 2) SH7 (P8.5)
SPI6_MOSI: HITL (MCU) SH3 (U3.129), HITL (INTRFACE 2) SH7 (R72.2)
SPI6_SCK: HITL (MCU) SH3 (U3.128), HITL (INTRFACE 2) SH7 (R71.2)
TELEM: HITL (MCU) SH3 (U3.79), HITL (INTRFACE 2) SH7 (J10.1)
UART4_RX: HITL (MCU) SH3 (U3.35), HITL (INTRFACE 2) SH7 (P12.2)
UART4_TX: HITL (MCU) SH3 (U3.34), HITL (INTRFACE 2) SH7 (P12.3)
USART2_RX: HITL (MCU) SH3 (U3.37), HITL (INTRFACE 2) SH7 (P13.2)
USART2_TX: HITL (MCU) SH3 (U3.36), HITL (INTRFACE 2) SH7 (P13.3)
USB_VBUS_SNS: HITL (PWR) SH2 (D3.1 R1.1 R4.2), HITL (MCU) SH3 (U3.101)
